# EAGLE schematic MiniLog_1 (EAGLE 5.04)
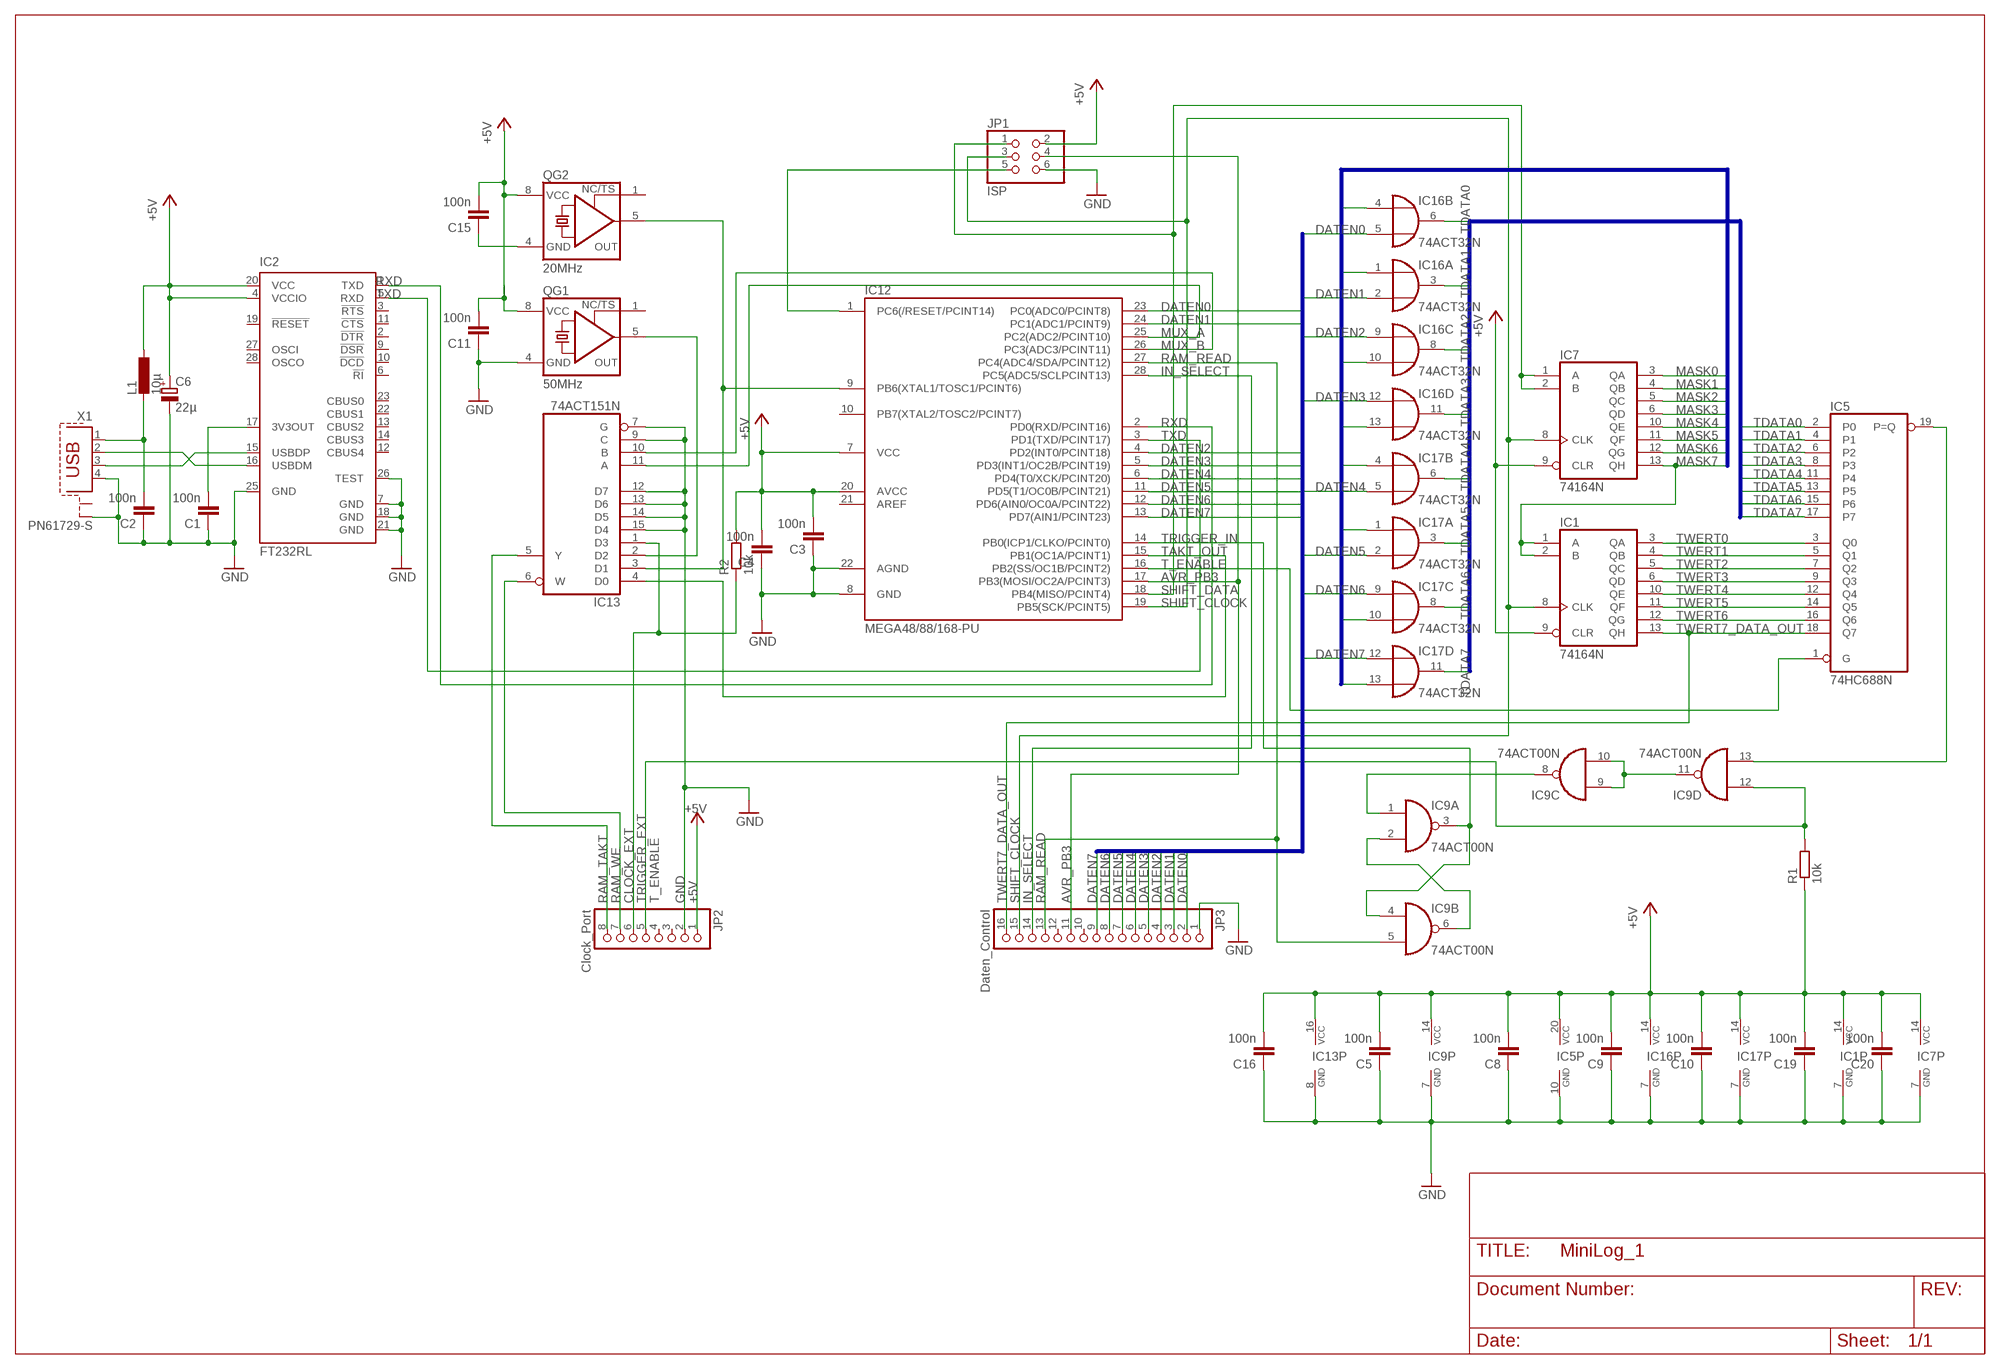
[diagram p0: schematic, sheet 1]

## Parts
C1  100n  C-EU025-025X050  [C025-025X050]
C2  100n  C-EU025-025X050  [C025-025X050]
C3  100n  C-EU025-025X050  [C025-025X050]
C4  100n  C-EU025-025X050  [C025-025X050]
C5  100n  C-EU025-025X050  [C025-025X050]
C6  22µ  CPOL-EUE2.5-6  [E2,5-6]
C8  100n  C-EU025-025X050  [C025-025X050]
C9  100n  C-EU025-025X050  [C025-025X050]
C10  100n  C-EU025-025X050  [C025-025X050]
C11  100n  C-EU025-025X050  [C025-025X050]
C15  100n  C-EU025-025X050  [C025-025X050]
C16  100n  C-EU025-025X050  [C025-025X050]
C19  100n  C-EU025-025X050  [C025-025X050]
C20  100n  C-EU025-025X050  [C025-025X050]
IC1  74164N  [DIL14]
IC2  FT232RL  [SSOP28]
IC5  74HC688N  [DIL20]
IC7  74164N  [DIL14]
IC9  74ACT00N  [DIL14]
IC12  MEGA48/88/168-PU  [DIL28-3]
IC13  74ACT151N  [DIL16]
IC16  74ACT32N  [DIL14]
IC17  74ACT32N  [DIL14]
JP1  ISP  PINHD-2X3  [2X03]
JP2  Clock_Port  PINHD-1X8  [1X08]
JP3  Daten_Control  PINHD-1X16  [1X16]
L1  10µ  L-EUIRF-1  [IRF-1]
QG1  50MHz  XO-8  [DIL08S]
QG2  20MHz  XO-8  [DIL08S]
R1  10k  R-EU_0207/10  [0207/10]
R2  10k  R-EU_0207/10  [0207/10]
X1  PN61729-S  [PN61729-S]

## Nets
+5V: C3.2 C4.2 C5.2 C6.+ C8.2 C9.2 C10.2 C11.2 C15.2 C16.2 C19.2 C20.2 IC1.9(CLR) IC1.14(VCC) IC2.4(VCCIO) IC2.20(VCC) IC5.20(VCC) IC7.9(CLR) IC7.14(VCC) IC9.14(P:VCC) IC12.7(VCC) IC12.20(AVCC) IC13.16(VCC) IC16.14(P:VCC) IC17.14(P:VCC) JP1.2 JP2.1 L1.1 QG1.8(VCC) QG2.8(VCC) R1.1 R2.2
AVR_PB3: IC12.17(PB3(MOSI/OC2A/PCINT3)) JP1.4 JP3.11
CLOCK_EXT: IC13.1(D3) JP2.6 R2.1
DATEN0: IC12.23(PC0(ADC0/PCINT8)) IC16.5(B:I1) JP3.2
DATEN1: IC12.24(PC1(ADC1/PCINT9)) IC16.2(A:I1) JP3.3
DATEN2: IC12.4(PD2(INT0/PCINT18)) IC16.9(C:I0) JP3.4
DATEN3: IC12.5(PD3(INT1/OC2B/PCINT19)) IC16.12(D:I0) JP3.5
DATEN4: IC12.6(PD4(T0/XCK/PCINT20)) IC17.5(B:I1) JP3.6
DATEN5: IC12.11(PD5(T1/OC0B/PCINT21)) IC17.2(A:I1) JP3.7
DATEN6: IC12.12(PD6(AIN0/OC0A/PCINT22)) IC17.9(C:I0) JP3.8
DATEN7: IC12.13(PD7(AIN1/PCINT23)) IC17.12(D:I0) JP3.9
GND: C1.1 C2.1 C3.1 C4.1 C5.1 C6.- C8.1 C9.1 C10.1 C11.1 C16.1 C19.1 C20.1 IC1.7(GND) IC2.7(GND) IC2.18(GND) IC2.21(GND) IC2.25(GND) IC2.26(TEST) IC5.10(GND) IC7.7(GND) IC9.7(P:GND) IC12.8(GND) IC12.22(AGND) IC13.7(G) IC13.8(GND) IC13.9(C) IC13.12(D7) IC13.13(D6) IC13.14(D5) IC13.15(D4) IC16.7(P:GND) IC17.7(P:GND) JP1.6 JP2.2 JP3.1 QG1.4(GND) X1.4 X1.S2
IN_SELECT: IC12.28(PC5(ADC5/SCLPCINT13)) JP3.14
MASK0: IC7.3(QA) IC16.4(B:I0)
MASK1: IC7.4(QB) IC16.1(A:I0)
MASK2: IC7.5(QC) IC16.10(C:I1)
MASK3: IC7.6(QD) IC16.13(D:I1)
MASK4: IC7.10(QE) IC17.4(B:I0)
MASK5: IC7.11(QF) IC17.1(A:I0)
MASK6: IC7.12(QG) IC17.10(C:I1)
MASK7: IC1.1(A) IC1.2(B) IC7.13(QH) IC17.13(D:I1)
MUX_A: IC12.25(PC2(ADC2/PCINT10)) IC13.11(A)
MUX_B: IC12.26(PC3(ADC3/PCINT11)) IC13.10(B)
N$1: IC9.1(A:I0) IC9.8(C:O)
N$2: IC9.9(C:I0) IC9.10(C:I1) IC9.11(D:O)
N$3: C2.2 L1.2 X1.1
N$4: C1.2 IC2.17(3V3OUT)
N$5: IC2.16(USBDM) X1.2
N$6: IC2.15(USBDP) X1.3
N$7: IC9.2(A:I1) IC9.6(B:O)
N$8: IC5.19(P=Q) IC9.13(D:I1)
N$9: IC12.1(PC6(/RESET/PCINT14)) JP1.5
N$33: IC12.9(PB6(XTAL1/TOSC1/PCINT6)) IC13.3(D1) QG2.5(OUT)
N$38: IC13.2(D2) QG1.5(OUT)
N$39: C15.1 QG2.4(GND)
RAM_READ: IC9.5(B:I1) IC12.27(PC4(ADC4/SDA/PCINT12)) JP3.13
RAM_TAKT: IC13.5(Y) JP2.8
RAM_WE: IC13.6(W) JP2.7
RXD: IC2.1(TXD) IC12.2(PD0(RXD/PCINT16))
SHIFT_CLOCK: IC1.8(CLK) IC7.8(CLK) IC12.19(PB5(SCK/PCINT5)) JP1.3 JP3.15
SHIFT_DATA: IC7.1(A) IC7.2(B) IC12.18(PB4(MISO/PCINT4)) JP1.1
T_ENABLE: IC5.1(G) IC12.16(PB2(SS/OC1B/PCINT2))
TAKT_OUT: IC12.15(PB1(OC1A/PCINT1)) IC13.4(D0)
TDATA0: IC5.2(P0) IC16.6(B:O)
TDATA1: IC5.4(P1) IC16.3(A:O)
TDATA2: IC5.6(P2) IC16.8(C:O)
TDATA3: IC5.8(P3) IC16.11(D:O)
TDATA4: IC5.11(P4) IC17.6(B:O)
TDATA5: IC5.13(P5) IC17.3(A:O)
TDATA6: IC5.15(P6) IC17.8(C:O)
TDATA7: IC5.17(P7) IC17.11(D:O)
TRIGGER_EXT: IC9.12(D:I0) JP2.5 R1.2
TRIGGER_IN: IC9.3(A:O) IC9.4(B:I0) IC12.14(PB0(ICP1/CLKO/PCINT0))
TWERT0: IC1.3(QA) IC5.3(Q0)
TWERT1: IC1.4(QB) IC5.5(Q1)
TWERT2: IC1.5(QC) IC5.7(Q2)
TWERT3: IC1.6(QD) IC5.9(Q3)
TWERT4: IC1.10(QE) IC5.12(Q4)
TWERT5: IC1.11(QF) IC5.14(Q5)
TWERT6: IC1.12(QG) IC5.16(Q6)
TWERT7_DATA_OUT: IC1.13(QH) IC5.18(Q7) JP3.16
TXD: IC2.5(RXD) IC12.3(PD1(TXD/PCINT17))
Unconnected: IC2.2(!DTR) IC2.3(!RTS) IC2.6(!RI) IC2.9(!DSR) IC2.10(!DCD) IC2.11(!CTS) IC2.12(CBUS4) IC2.13(CBUS2) IC2.14(CBUS3) IC2.19(!RESET) IC2.22(CBUS1) IC2.23(CBUS0) IC2.27(OSCI) IC2.28(OSCO) IC12.10(PB7(XTAL2/TOSC2/PCINT7)) IC12.21(AREF) JP2.3 JP2.4 JP3.10 JP3.12 QG1.1(TS) QG2.1(TS) X1.S1

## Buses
MASK[0..7]
DATEN[0..7]
TDATA[0..7]

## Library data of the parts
C1-C5 C8-C11 C15 C16 C19 C20 = rcl:C-EU: CAPACITOR, European symbol
C6 = rcl:CPOL-EU: POLARIZED CAPACITOR, European symbol
IC1 IC7 = 74xx-eu:74*164: 8-bit parallel out SHIFT REGISTER
IC2 = ftdichip:FT232R: Source: http://www.ftdichip.com/Documents/DataSheets/DS_FT232R_v104.pdf
IC5 = 74xx-eu:74*688: 8-bit MAGNITUDE/IDENTITY COMPARATOR, totem pole
IC9 = 74xx-eu:74*00: Quad 2-input NAND gate
IC12 = avr-4:MEGA48/88/168-PU
IC13 = 74xx-eu:74*151: Data SELECTOR/MULTIPLEXER
IC16 IC17 = 74xx-eu:74*32: Quad 2-input OR gate
JP1 = pinhead:PINHD-2X3: PIN HEADER
JP2 = pinhead:PINHD-1X8: PIN HEADER
JP3 = pinhead:PINHD-1X16: PIN HEADER
L1 = rcl:L-EU: INDUCTOR, European symbol
QG1 QG2 = crystal:XO-: CRYSTAL
R1 R2 = rcl:R-EU_: RESISTOR, European symbol
X1 = con-berg:PN61729-S: BERG USB connector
